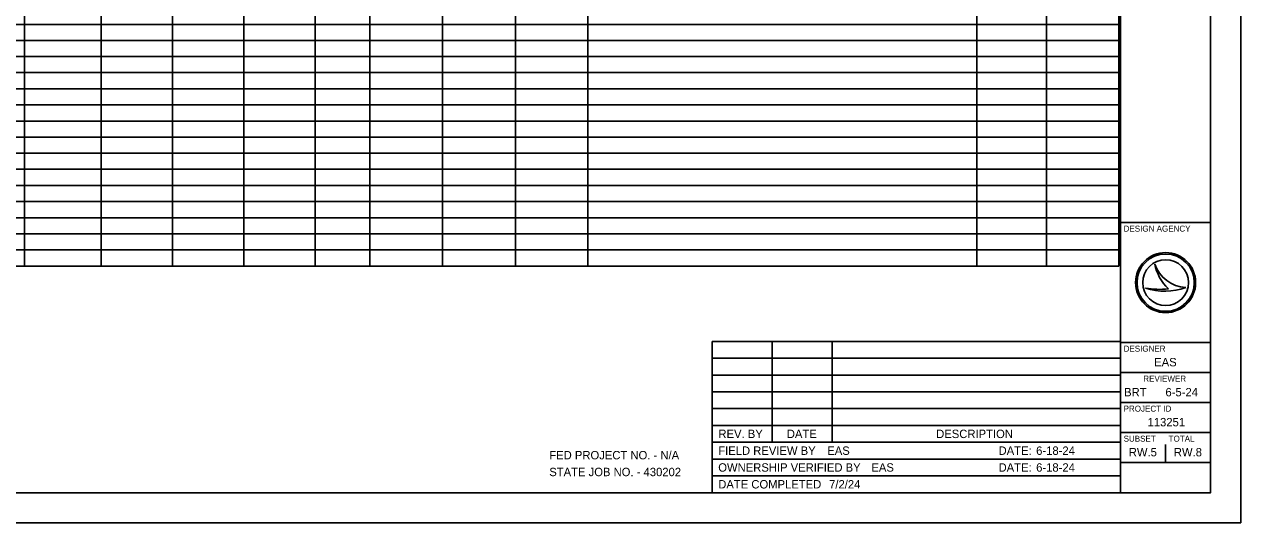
# Model space of a CAD drawing. Extents: x 0 to 34, y 0 to 22.
# Drawn here: x 13.74 to 34, y 0 to 8.3 of the extents above; entities that cross this region are included whole.
import ezdxf

# ---------------------------------------------------------------- set-up
doc = ezdxf.new("R2010")
doc.units = 0
for name, color, linetype in [('SH_Border', 7, 'Continuous'), ('SH_Cut_Line', 7, 'Continuous'), ('SH_Data', 7, 'Continuous'), ('SH_Text', 7, 'Continuous')]:
    doc.layers.add(name, color=color, linetype=linetype)

msp = doc.modelspace()

# ---------------------------------------------------------------- linework, layer by layer
at = {"layer": 'SH_Border'}
for p, q in [((32, 0.5), (32, 21.5)), ((32, 5), (33.5, 5)), ((32, 3), (33.5, 3)), ((32, 2.5), (33.5, 2.5)), ((32, 2), (33.5, 2)), ((32, 1.5), (33.5, 1.5)), ((32, 1), (33.5, 1))]:
    msp.add_line(p, q, dxfattribs=at)
msp.add_lwpolyline([(1.5, 21.5), (33.5, 21.5), (33.5, 0.5), (1.5, 0.5)], close=True, dxfattribs=at)
at = {"layer": 'SH_Cut_Line'}
msp.add_lwpolyline([(0, 0), (34, 0), (34, 22), (0, 22)], close=True, dxfattribs=at)
at = {"layer": 'SH_Data'}
for p, q in [((32.567, 4.31), (32.567, 4.31)), ((32.417, 3.91), (32.417, 3.91)), ((32.75, 4), (32.75, 4)), ((33.087, 3.919), (33.087, 3.919)), ((32.75, 1), (32.75, 1.3))]:
    msp.add_line(p, q, dxfattribs=at)
for radius in [0.5, 0.477, 0.477, 0.382]:
    msp.add_circle((32.75, 4), radius, dxfattribs=at)
for centre, radius, start, end in [((33.116, 4.498), 0.58, 198.9257, 198.9319), ((33.347, 4.47), 0.796, 191.6379, 191.6421), ((33.116, 4.498), 0.58, 198.9319, 267.1657), ((33.347, 4.47), 0.796, 191.6421, 226.0947), ((32.739, 4.87), 1.013, 251.4576, 290.0832), ((32.648, 5.154), 1.266, 259.4964, 259.4995), ((32.739, 4.87), 1.013, 251.4527, 251.4576), ((32.648, 5.154), 1.266, 259.4995, 276.6672)]:
    msp.add_arc(centre, radius, start, end, dxfattribs=at)
at = {"layer": 'SH_Text'}
for p, q in [((13.737, 9.11), (13.737, 8.304)), ((15.015, 9.11), (15.015, 8.304)), ((16.205, 9.11), (16.205, 8.304)), ((17.394, 9.11), (17.394, 8.304)), ((18.583, 9.11), (18.583, 8.304)), ((19.491, 9.11), (19.491, 8.304)), ((20.705, 9.11), (20.705, 8.304)), ((21.92, 9.11), (21.92, 8.304)), ((23.122, 9.11), (23.122, 8.304)), ((29.605, 9.11), (29.605, 8.304)), ((30.768, 9.11), (30.768, 8.304)), ((31.97, 9.11), (31.97, 8.304)), ((12.599, 8.304), (13.737, 8.304)), ((13.737, 8.304), (16.205, 8.304)), ((13.737, 8.304), (13.737, 8.036)), ((15.015, 8.304), (15.015, 8.036)), ((16.205, 8.304), (30.768, 8.304)), ((16.205, 8.304), (16.205, 8.036)), ((17.394, 8.304), (17.394, 8.036)), ((18.583, 8.304), (18.583, 8.036)), ((19.491, 8.304), (19.491, 8.036)), ((20.705, 8.304), (20.705, 8.036)), ((21.92, 8.304), (21.92, 8.036)), ((23.122, 8.304), (23.122, 8.036)), ((29.605, 8.304), (29.605, 8.036)), ((30.768, 8.304), (31.97, 8.304)), ((30.768, 8.304), (30.768, 8.036)), ((31.97, 8.304), (31.97, 8.036)), ((12.599, 8.036), (13.737, 8.036)), ((13.737, 8.036), (16.205, 8.036)), ((13.737, 8.036), (13.737, 7.767)), ((15.015, 8.036), (15.015, 7.767)), ((16.205, 8.036), (30.768, 8.036)), ((16.205, 8.036), (16.205, 7.767)), ((17.394, 8.036), (17.394, 7.767)), ((18.583, 8.036), (18.583, 7.767)), ((19.491, 8.036), (19.491, 7.767)), ((20.705, 8.036), (20.705, 7.767)), ((21.92, 8.036), (21.92, 7.767)), ((23.122, 8.036), (23.122, 7.767)), ((29.605, 8.036), (29.605, 7.767)), ((30.768, 8.036), (31.97, 8.036)), ((30.768, 8.036), (30.768, 7.767)), ((31.97, 8.036), (31.97, 7.767)), ((12.599, 7.767), (13.737, 7.767)), ((13.737, 7.767), (16.205, 7.767)), ((13.737, 7.767), (13.737, 6.962)), ((15.015, 7.767), (15.015, 6.962)), ((16.205, 7.767), (30.768, 7.767)), ((16.205, 7.767), (16.205, 6.962)), ((17.394, 7.767), (17.394, 6.962)), ((18.583, 7.767), (18.583, 6.962)), ((19.491, 7.767), (19.491, 6.962)), ((20.705, 7.767), (20.705, 6.962)), ((21.92, 7.767), (21.92, 6.962)), ((23.122, 7.767), (23.122, 6.962)), ((29.605, 7.767), (29.605, 6.962)), ((30.768, 7.767), (31.97, 7.767)), ((30.768, 7.767), (30.768, 6.962)), ((31.97, 7.767), (31.97, 6.962)), ((12.599, 7.499), (13.737, 7.499)), ((13.737, 7.499), (16.205, 7.499)), ((16.205, 7.499), (30.768, 7.499)), ((30.768, 7.499), (31.97, 7.499)), ((12.599, 7.23), (13.737, 7.23)), ((13.737, 7.23), (16.205, 7.23)), ((16.205, 7.23), (30.768, 7.23)), ((30.768, 7.23), (31.97, 7.23)), ((12.599, 6.962), (13.737, 6.962)), ((13.737, 6.962), (16.205, 6.962)), ((13.737, 6.962), (13.737, 6.693)), ((15.015, 6.962), (15.015, 6.693)), ((16.205, 6.962), (30.768, 6.962)), ((16.205, 6.962), (16.205, 6.693)), ((17.394, 6.962), (17.394, 6.693)), ((18.583, 6.962), (18.583, 6.693)), ((19.491, 6.962), (19.491, 6.693)), ((20.705, 6.962), (20.705, 6.693)), ((21.92, 6.962), (21.92, 6.693)), ((23.122, 6.962), (23.122, 6.693)), ((29.605, 6.962), (29.605, 6.693)), ((30.768, 6.962), (31.97, 6.962)), ((30.768, 6.962), (30.768, 6.693)), ((31.97, 6.962), (31.97, 6.693)), ((12.599, 6.693), (13.737, 6.693)), ((13.737, 6.693), (16.205, 6.693)), ((13.737, 6.693), (13.737, 4.276)), ((15.015, 6.693), (15.015, 4.276)), ((16.205, 6.693), (30.768, 6.693)), ((16.205, 6.693), (16.205, 4.276)), ((17.394, 6.693), (17.394, 4.276)), ((18.583, 6.693), (18.583, 4.276)), ((19.491, 6.693), (19.491, 4.276)), ((20.705, 6.693), (20.705, 4.276)), ((21.92, 6.693), (21.92, 4.276)), ((23.122, 6.693), (23.122, 4.276)), ((29.605, 6.693), (29.605, 4.276)), ((30.768, 6.693), (31.97, 6.693)), ((30.768, 6.693), (30.768, 4.276)), ((31.97, 6.693), (31.97, 4.276)), ((12.599, 6.425), (13.737, 6.425)), ((13.737, 6.425), (16.205, 6.425)), ((16.205, 6.425), (30.768, 6.425)), ((30.768, 6.425), (31.97, 6.425)), ((12.599, 6.156), (13.737, 6.156)), ((13.737, 6.156), (16.205, 6.156)), ((16.205, 6.156), (30.768, 6.156)), ((30.768, 6.156), (31.97, 6.156)), ((12.599, 5.888), (13.737, 5.888)), ((13.737, 5.888), (16.205, 5.888)), ((16.205, 5.888), (30.768, 5.888)), ((30.768, 5.888), (31.97, 5.888)), ((12.599, 5.619), (13.737, 5.619)), ((13.737, 5.619), (16.205, 5.619)), ((16.205, 5.619), (30.768, 5.619)), ((30.768, 5.619), (31.97, 5.619)), ((12.599, 5.351), (13.737, 5.351)), ((13.737, 5.351), (16.205, 5.351)), ((16.205, 5.351), (30.768, 5.351)), ((30.768, 5.351), (31.97, 5.351)), ((12.599, 5.082), (13.737, 5.082)), ((13.737, 5.082), (16.205, 5.082)), ((16.205, 5.082), (30.768, 5.082)), ((30.768, 5.082), (31.97, 5.082)), ((12.599, 4.814), (13.737, 4.814)), ((13.737, 4.814), (16.205, 4.814)), ((16.205, 4.814), (30.768, 4.814)), ((30.768, 4.814), (31.97, 4.814)), ((12.599, 4.545), (13.737, 4.545)), ((13.737, 4.545), (16.205, 4.545)), ((16.205, 4.545), (30.768, 4.545)), ((30.768, 4.545), (31.97, 4.545)), ((12.599, 4.276), (13.737, 4.276)), ((13.737, 4.276), (16.205, 4.276)), ((16.205, 4.276), (30.768, 4.276)), ((30.768, 4.276), (31.97, 4.276)), ((25.197, 3.02), (25.197, 0.5)), ((25.197, 3.02), (32, 3.02)), ((26.197, 3.02), (26.197, 1.34)), ((27.197, 3.02), (27.197, 1.34)), ((25.197, 2.74), (32, 2.74)), ((25.197, 2.46), (32, 2.46)), ((25.197, 2.18), (32, 2.18)), ((25.197, 1.9), (32, 1.9)), ((25.197, 1.62), (32, 1.62)), ((25.197, 1.34), (32, 1.34)), ((25.197, 1.06), (32, 1.06)), ((25.197, 0.78), (32, 0.78)), ((32, 0.5), (32, 0.5))]:
    msp.add_line(p, q, dxfattribs=at)

# ---------------------------------------------------------------- texts
at = {"layer": 'SH_Data'}
for s, height, p in [('DESIGN AGENCY', 0.1, (32.05, 4.85)), ('DESIGNER', 0.1, (32.05, 2.85)), ('EAS', 0.14, (32.559, 2.605)), ('REVIEWER', 0.1, (32.378, 2.35)), ('BRT', 0.14, (32.058, 2.105)), ('6-5-24', 0.14, (32.747, 2.105)), ('PROJECT ID', 0.1, (32.05, 1.85)), ('SUBSET', 0.1, (32.05, 1.35)), ('TOTAL', 0.1, (32.8, 1.35)), ('RW.5', 0.14, (32.136, 1.105)), ('RW.8', 0.14, (32.887, 1.105))]:
    msp.add_text(s, height=height, dxfattribs=at).set_placement(p)
at = {"layer": 'SH_Text'}
for s, p in [('113251', (32.449, 1.605)), ('REV. BY', (25.3, 1.41)), ('DATE', (26.439, 1.41)), ('DESCRIPTION', (28.927, 1.41)), ('FIELD REVIEW BY', (25.297, 1.13)), ('EAS                      ', (27.113, 1.13)), ('DATE:', (29.967, 1.13)), ('6-18-24 ', (30.593, 1.13)), ('FED PROJECT NO. - N/A', (22.482, 1.055)), ('STATE JOB NO. - 430202', (22.482, 0.775)), ('OWNERSHIP VERIFIED BY', (25.297, 0.85)), ('EAS               ', (27.848, 0.85)), ('DATE:', (29.967, 0.85)), ('6-18-24 ', (30.593, 0.85)), ('DATE COMPLETED', (25.297, 0.57)), ('7/2/24                              ', (27.144, 0.57))]:
    msp.add_text(s, height=0.14, dxfattribs=at).set_placement(p)

doc.saveas('drawing.dxf')
